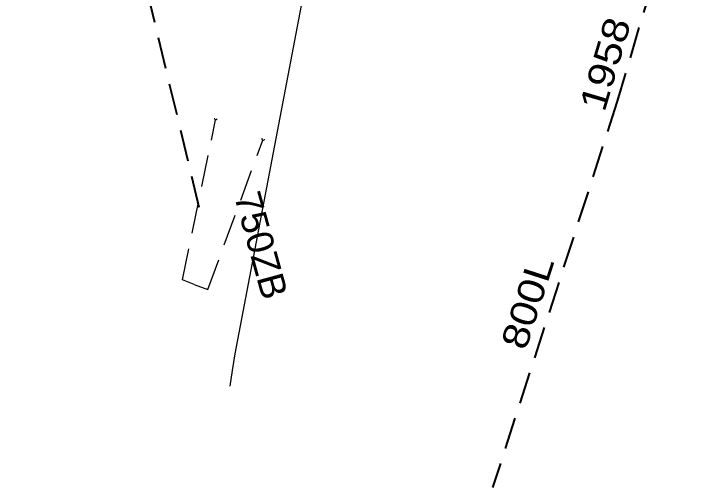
# Model space of a CAD drawing. Extents: x -740851 to -738888, y -1041382 to -1040235.
# Drawn here: x -739045.2 to -739019.6, y -1041357.66 to -1041339.73 of the extents above; entities that cross this region are included whole.
import ezdxf

# ---------------------------------------------------------------- set-up
doc = ezdxf.new("R2010")
doc.units = 0
doc.header["$LTSCALE"] = 0.4
doc.linetypes.add('MEDIUM_DASHED', pattern=[4.5, 3, -1.5])
doc.layers.add('18', color=7, linetype='Continuous', lineweight=13)
doc.layers.add('8', color=7, linetype='Continuous', lineweight=13)

msp = doc.modelspace()

# ---------------------------------------------------------------- linework, layer by layer
at = {"layer": '18', "linetype": 'MEDIUM_DASHED', "lineweight": 40}
msp.add_line((-739038.18, -1041347.07), (-739045.2, -1041317.71), dxfattribs=at)
at = {"layer": '8'}
for p, q in [((-739037.594, -1041343.693), (-739037.6, -1041343.692)), ((-739037.502, -1041343.712), (-739037.508, -1041343.711)), ((-739035.799, -1041344.465), (-739035.805, -1041344.463)), ((-739035.711, -1041344.497), (-739035.716, -1041344.495))]:
    msp.add_line(p, q, dxfattribs=at)
at = {"layer": '8', "linetype": 'MEDIUM_DASHED', "lineweight": 40}
msp.add_lwpolyline([(-739018.255, -1041332.822), (-739019.505, -1041333.359), (-739022.37, -1041343.05), (-739027.082, -1041357.662)], dxfattribs=at)
at = {"layer": '8', "lineweight": 25}
msp.add_lwpolyline([(-739037.009, -1041353.834), (-739036.916, -1041353.231), (-739036.82, -1041352.61), (-739033.31, -1041334.18)], dxfattribs=at)
at = {"layer": '8'}
for points in [[(-739037.6, -1041343.692), (-739037.601, -1041343.697), (-739037.601, -1041343.702), (-739037.601, -1041343.707), (-739037.6, -1041343.712), (-739037.598, -1041343.718), (-739037.596, -1041343.722), (-739037.594, -1041343.727), (-739037.591, -1041343.732), (-739037.587, -1041343.735), (-739037.584, -1041343.739), (-739037.58, -1041343.743), (-739037.575, -1041343.746), (-739037.57, -1041343.748), (-739037.566, -1041343.75), (-739037.561, -1041343.751), (-739037.556, -1041343.752), (-739037.551, -1041343.752), (-739037.546, -1041343.752), (-739037.54, -1041343.751), (-739037.535, -1041343.749), (-739037.53, -1041343.747), (-739037.526, -1041343.745), (-739037.521, -1041343.742), (-739037.518, -1041343.738), (-739037.514, -1041343.735), (-739037.51, -1041343.731), (-739037.507, -1041343.726), (-739037.505, -1041343.721), (-739037.503, -1041343.717), (-739037.502, -1041343.712)], [(-739037.594, -1041343.693), (-739037.595, -1041343.698), (-739037.595, -1041343.702), (-739037.595, -1041343.707), (-739037.594, -1041343.712), (-739037.593, -1041343.716), (-739037.591, -1041343.72), (-739037.589, -1041343.725), (-739037.587, -1041343.728), (-739037.584, -1041343.732), (-739037.58, -1041343.735), (-739037.577, -1041343.737), (-739037.573, -1041343.74), (-739037.568, -1041343.742), (-739037.565, -1041343.744), (-739037.56, -1041343.745), (-739037.555, -1041343.746), (-739037.551, -1041343.746), (-739037.546, -1041343.746), (-739037.541, -1041343.745), (-739037.537, -1041343.743), (-739037.533, -1041343.742), (-739037.528, -1041343.74), (-739037.525, -1041343.738), (-739037.521, -1041343.734), (-739037.518, -1041343.731), (-739037.515, -1041343.727), (-739037.513, -1041343.724), (-739037.511, -1041343.719), (-739037.509, -1041343.715), (-739037.508, -1041343.711)], [(-739035.805, -1041344.463), (-739035.806, -1041344.467), (-739035.807, -1041344.473), (-739035.808, -1041344.478), (-739035.808, -1041344.483), (-739035.807, -1041344.489), (-739035.805, -1041344.493), (-739035.804, -1041344.498), (-739035.801, -1041344.503), (-739035.799, -1041344.508), (-739035.796, -1041344.512), (-739035.792, -1041344.516), (-739035.788, -1041344.52), (-739035.784, -1041344.523), (-739035.78, -1041344.525), (-739035.775, -1041344.527), (-739035.77, -1041344.529), (-739035.765, -1041344.529), (-739035.76, -1041344.53), (-739035.755, -1041344.53), (-739035.749, -1041344.529), (-739035.744, -1041344.527), (-739035.739, -1041344.526), (-739035.734, -1041344.524), (-739035.73, -1041344.521), (-739035.726, -1041344.518), (-739035.721, -1041344.515), (-739035.718, -1041344.511), (-739035.715, -1041344.506), (-739035.712, -1041344.502), (-739035.711, -1041344.497)], [(-739035.799, -1041344.465), (-739035.801, -1041344.47), (-739035.801, -1041344.474), (-739035.802, -1041344.479), (-739035.801, -1041344.483), (-739035.801, -1041344.488), (-739035.8, -1041344.492), (-739035.799, -1041344.497), (-739035.797, -1041344.501), (-739035.795, -1041344.505), (-739035.791, -1041344.508), (-739035.788, -1041344.511), (-739035.785, -1041344.515), (-739035.781, -1041344.517), (-739035.778, -1041344.52), (-739035.773, -1041344.521), (-739035.768, -1041344.523), (-739035.764, -1041344.523), (-739035.759, -1041344.524), (-739035.755, -1041344.524), (-739035.75, -1041344.523), (-739035.746, -1041344.523), (-739035.741, -1041344.521), (-739035.737, -1041344.519), (-739035.733, -1041344.517), (-739035.73, -1041344.514), (-739035.726, -1041344.511), (-739035.723, -1041344.508), (-739035.72, -1041344.503), (-739035.718, -1041344.5), (-739035.716, -1041344.495)]]:
    msp.add_lwpolyline(points, dxfattribs=at)
at = {"layer": '8', "linetype": 'MEDIUM_DASHED', "lineweight": 25}
for points in [[(-739038.366, -1041349.98), (-739038.815, -1041349.807), (-739037.56, -1041343.753)], [(-739038.366, -1041349.98), (-739037.849, -1041350.179), (-739035.775, -1041344.529)]]:
    msp.add_lwpolyline(points, dxfattribs=at)

# ---------------------------------------------------------------- texts
at = {"layer": '18', "width": 1.05}
msp.add_text('750ZB', height=1, rotation=285.35, dxfattribs=at).set_placement((-739036.864, -1041346.634))
at = {"layer": '8', "width": 1.2}
for s, rotation, p in [('1958', 73.53, (-739022.851, -1041343.495)), ('800L', 72.127, (-739025.832, -1041352.513))]:
    msp.add_text(s, height=1, rotation=rotation, dxfattribs=at).set_placement(p)

doc.saveas('drawing.dxf')
